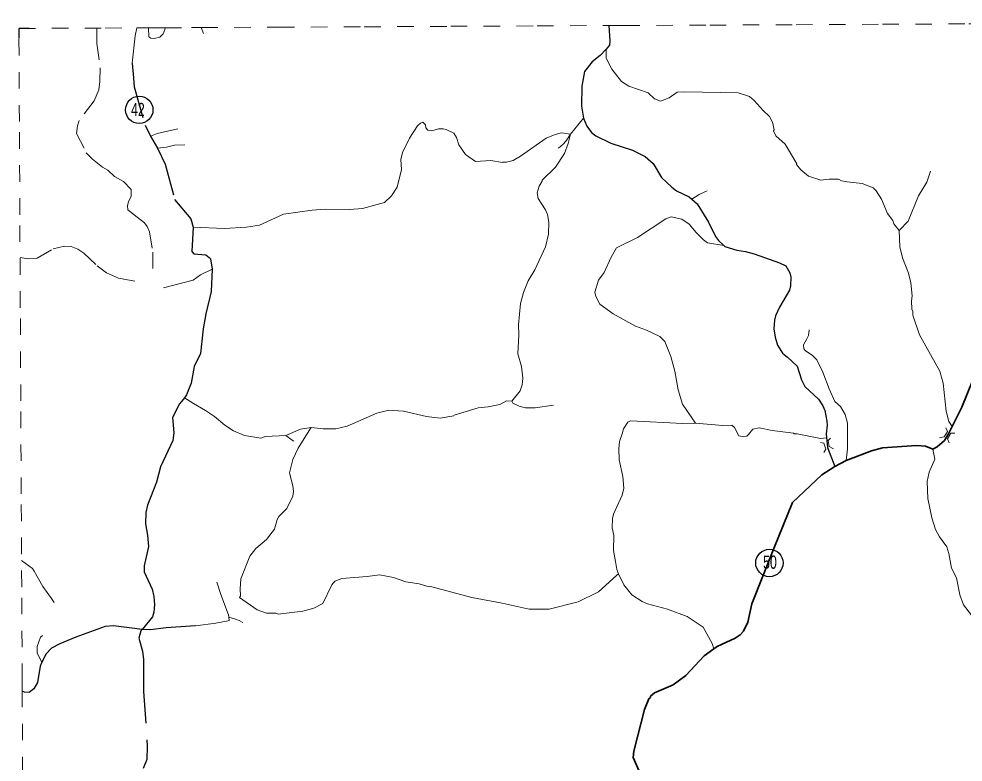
# Model space of a CAD drawing. Extents: x 423 to 448.8, y 7456.3 to 7484.
# Drawn here: x 422.99 to 428.72, y 7479.48 to 7483.99 of the extents above; entities that cross this region are included whole.
import ezdxf
from ezdxf.enums import TextEntityAlignment as Align

# ---------------------------------------------------------------- set-up
doc = ezdxf.new("R2010")
doc.units = 0
doc.header["$LTSCALE"] = 0.032
for name, pattern in [('LONG_DASHED', [7.5, 6, -1.5]), ('MEDIUM_DASHED', [4.5, 3, -1.5]), ('SHORT_DASHED', [2.7, 1.5, -1.2])]:
    doc.linetypes.add(name, pattern=pattern)
for name, color, linetype, lineweight in [('11', 7, 'Continuous', 13), ('13', 7, 'Continuous', 25), ('2', 7, 'Continuous', 35), ('35', 7, 'SHORT_DASHED', 13), ('4', 7, 'LONG_DASHED', 25), ('5', 7, 'LONG_DASHED', 13), ('6', 7, 'MEDIUM_DASHED', 13), ('63', 7, 'Continuous', 25), ('7', 7, 'Continuous', 13)]:
    doc.layers.add(name, color=color, linetype=linetype, lineweight=lineweight)
doc.layers.add('61', color=7, linetype='Continuous')

msp = doc.modelspace()

# ---------------------------------------------------------------- linework, layer by layer
at = {"layer": '11'}
for points in [[(428.6171, 7481.5036), (428.6262, 7481.4826), (428.6052, 7481.4497), (428.5787, 7481.4442)], [(428.6363, 7481.414), (428.6262, 7481.4369), (428.6473, 7481.4716), (428.6711, 7481.4716)], [(427.857, 7481.4151), (427.8759, 7481.4102), (427.8877, 7481.3745), (427.8767, 7481.3535)], [(427.916, 7481.4405), (427.902, 7481.4262), (427.9077, 7481.3902), (427.9343, 7481.3762)]]:
    msp.add_lwpolyline(points, dxfattribs=at)
at = {"layer": '13'}
for centre in [(423.7237, 7483.4329), (427.5458, 7480.684)]:
    msp.add_circle(centre, 0.083, dxfattribs=at)
at = {"layer": '2'}
msp.add_lwpolyline([(426.7706, 7479.388), (426.7191, 7479.5039), (426.7242, 7479.5426), (426.7887, 7479.7951), (426.8153, 7479.8603), (426.8247, 7479.868), (426.8256, 7479.8758), (426.8488, 7479.8956), (426.9622, 7479.9445), (427.0386, 7480.002), (427.1511, 7480.1205), (427.2096, 7480.1634), (427.2284, 7480.1772), (427.3383, 7480.2279), (427.3692, 7480.2477), (427.3899, 7480.2709), (427.4156, 7480.3259), (427.4397, 7480.4358), (427.5728, 7480.7716), (427.6859, 7481.0507), (427.865, 7481.2198), (427.9421, 7481.2701), (428.0118, 7481.3054), (428.1647, 7481.3636), (428.2321, 7481.3822), (428.4377, 7481.3968), (428.4926, 7481.3933), (428.537, 7481.3736), (428.5638, 7481.3893), (428.6077, 7481.4277), (428.6343, 7481.4715), (428.6549, 7481.5131), (428.7125, 7481.6296), (428.7786, 7481.7893)], dxfattribs=at)
at = {"layer": '35'}
for points in [[(426.5714, 7483.9447), (426.6604, 7483.9451), (427.1842, 7483.9476), (427.7081, 7483.9501), (428.232, 7483.9526), (428.7559, 7483.9551), (429.2797, 7483.9575), (429.8036, 7483.9599), (430.3275, 7483.9623), (430.8513, 7483.9647), (431.3752, 7483.9671), (431.8991, 7483.9695), (432.4229, 7483.9718), (432.9468, 7483.9741), (433.4707, 7483.9764), (433.9946, 7483.9787), (434.5184, 7483.981), (435.0423, 7483.9832), (435.5128, 7483.9852)], [(422.9932, 7483.927), (423.5171, 7483.9296), (423.7097, 7483.9306), (423.7804, 7483.9309), (423.8803, 7483.9314)], [(423.0136, 7479.9058), (423.0133, 7479.9732), (423.0104, 7480.538), (423.0075, 7481.1029), (423.0047, 7481.6677), (423.0018, 7482.2325), (422.999, 7482.7973), (422.9961, 7483.3622), (422.9932, 7483.927)], [(423.8803, 7483.9314), (424.041, 7483.9322), (424.0999, 7483.9325)], [(424.0999, 7483.9325), (424.5649, 7483.9348), (425.0887, 7483.9374), (425.6126, 7483.94), (426.1365, 7483.9426), (426.5714, 7483.9447)], [(423.0308, 7476.517), (423.0305, 7476.5843), (423.0276, 7477.1491), (423.0247, 7477.7139), (423.0219, 7478.2787), (423.019, 7478.8436), (423.0161, 7479.4084), (423.0136, 7479.9058)]]:
    msp.add_lwpolyline(points, dxfattribs=at)
at = {"layer": '4'}
for points in [[(426.5714, 7483.9447), (426.5778, 7483.853), (426.5751, 7483.8255), (426.5568, 7483.8008), (426.5193, 7483.7628), (426.47, 7483.7251), (426.4253, 7483.6658), (426.4091, 7483.5774), (426.4056, 7483.4555), (426.4185, 7483.3833), (426.4383, 7483.3352), (426.4666, 7483.2965), (426.494, 7483.2751), (426.5843, 7483.2313), (426.7148, 7483.1883), (426.7921, 7483.1505), (426.8402, 7483.1076), (426.8917, 7483.0235), (426.9544, 7482.9634), (426.9828, 7482.9427), (427.0601, 7482.9058), (427.0756, 7482.892), (427.1073, 7482.8637), (427.176, 7482.752), (427.2198, 7482.6653), (427.2378, 7482.6404), (427.2695, 7482.6109), (427.2756, 7482.6052), (427.3486, 7482.5829), (427.4019, 7482.5743), (427.4534, 7482.5597), (427.608, 7482.5047), (427.6449, 7482.4876), (427.6707, 7482.4438), (427.6758, 7482.418), (427.6733, 7482.3647), (427.6672, 7482.339), (427.608, 7482.2359), (427.5831, 7482.1827), (427.5762, 7482.1569), (427.5728, 7482.1054), (427.5814, 7482.0538), (427.5943, 7482.0048), (427.6258, 7481.9563), (427.6561, 7481.9336), (427.7136, 7481.8778), (427.7403, 7481.7945), (427.7609, 7481.7549), (427.8433, 7481.6776), (427.8699, 7481.6373), (427.8819, 7481.6098), (427.894, 7481.5454), (427.8957, 7481.5196), (427.8897, 7481.4681), (427.8976, 7481.3847), (427.9421, 7481.2701)], [(423.6808, 7483.7168), (423.6851, 7483.6703), (423.6872, 7483.6521), (423.6934, 7483.5723), (423.7588, 7483.3402), (423.7921, 7483.2734), (423.8341, 7483.2012), (423.8797, 7483.1033), (423.9381, 7482.8895), (424.0356, 7482.7714), (424.0498, 7482.722), (424.0429, 7482.5743), (424.0541, 7482.5597), (424.1263, 7482.5528), (424.1469, 7482.5382), (424.1546, 7482.5287), (424.1649, 7482.4661), (424.1589, 7482.3321), (424.1263, 7482.1947), (424.1108, 7482.1054), (424.0948, 7481.9546), (424.0575, 7481.8752), (424.0378, 7481.7756), (424.0103, 7481.7043), (423.9975, 7481.6861), (423.9899, 7481.6753), (423.9677, 7481.6491), (423.9251, 7481.567), (423.9322, 7481.4733), (423.9278, 7481.4269), (423.8522, 7481.2671), (423.8274, 7481.1744), (423.7732, 7481.0353), (423.7629, 7480.9906), (423.7612, 7480.9219), (423.7741, 7480.8532), (423.7801, 7480.7845), (423.7526, 7480.6677), (423.7526, 7480.6307), (423.8016, 7480.5251), (423.8119, 7480.4804), (423.8162, 7480.4323), (423.8119, 7480.386), (423.8033, 7480.3568), (423.7405, 7480.2811)], [(423.7405, 7480.2811), (423.568, 7480.3018), (423.5165, 7480.2984), (423.3396, 7480.2348), (423.2417, 7480.1944), (423.1918, 7480.1678), (423.1592, 7480.1334), (423.133, 7480.0827), (423.1222, 7480.0579), (423.1062, 7479.9599), (423.084, 7479.92), (423.0562, 7479.8973), (423.0276, 7479.901), (423.0136, 7479.9058)], [(424.0641, 7480.3034), (423.8867, 7480.2907), (423.7915, 7480.2792), (423.7431, 7480.2808), (423.7405, 7480.2811)], [(423.7405, 7480.2811), (423.7334, 7480.2726), (423.7218, 7480.2284), (423.7423, 7480.1489), (423.7492, 7480.0991), (423.7492, 7479.9033), (423.7724, 7479.5735), (423.769, 7479.4911), (423.7475, 7479.4369)]]:
    msp.add_lwpolyline(points, dxfattribs=at)
at = {"layer": '5'}
msp.add_line((424.1138, 7483.8962), (424.0999, 7483.9325), dxfattribs=at)
for points in [[(423.7097, 7483.9306), (423.699, 7483.8816), (423.6808, 7483.7168)], [(423.7804, 7483.9309), (423.7824, 7483.8768), (423.7932, 7483.8672), (423.8136, 7483.8663), (423.8481, 7483.8748), (423.8685, 7483.8946), (423.8781, 7483.9201), (423.8803, 7483.9314)], [(429.3835, 7479.8883), (429.3724, 7480.0458), (429.3622, 7480.0783), (429.3419, 7480.1191), (429.3058, 7480.1432), (429.1276, 7480.0928), (429.0864, 7480.0868), (429.0412, 7480.0976), (428.8001, 7480.3335), (428.7712, 7480.3671), (428.724, 7480.4299), (428.7018, 7480.4915), (428.6805, 7480.5938), (428.6509, 7480.6527), (428.6352, 7480.7421), (428.6232, 7480.7819), (428.5785, 7480.8437), (428.5535, 7480.8875), (428.5321, 7480.958), (428.5077, 7481.0752), (428.504, 7481.1776), (428.516, 7481.2353), (428.55, 7481.314), (428.537, 7481.3736)], [(424.0641, 7480.3034), (424.1872, 7480.3182), (424.2529, 7480.3314)]]:
    msp.add_lwpolyline(points, dxfattribs=at)
at = {"layer": '6'}
for points in [[(423.4651, 7483.9293), (423.4658, 7483.8368), (423.4859, 7483.6892), (423.4847, 7483.6049), (423.4773, 7483.5538), (423.4495, 7483.4889), (423.3591, 7483.3694), (423.3482, 7483.3361), (423.3437, 7483.29), (423.4022, 7483.1729), (423.4405, 7483.1338), (423.5009, 7483.0848), (423.5319, 7483.0664), (423.5741, 7483.0285), (423.6283, 7482.9994), (423.6751, 7482.9497), (423.6745, 7482.9066), (423.6591, 7482.8765), (423.6521, 7482.8508), (423.6539, 7482.8276), (423.7114, 7482.7812), (423.7543, 7482.7478), (423.7715, 7482.7246), (423.7859, 7482.6935), (423.8051, 7482.57), (423.8073, 7482.4279)], [(423.0003, 7482.5376), (423.0495, 7482.5291), (423.1051, 7482.5339), (423.2012, 7482.5906), (423.2709, 7482.6061), (423.3095, 7482.6052), (423.3499, 7482.5872), (423.3868, 7482.564), (423.4688, 7482.4875), (423.5244, 7482.4443), (423.5985, 7482.4119), (423.6957, 7482.3933)], [(423.137, 7480.2433), (423.1244, 7480.2333), (423.1031, 7480.1781), (423.1031, 7480.1364), (423.133, 7480.0827)]]:
    msp.add_lwpolyline(points, dxfattribs=at)
at = {"layer": '63'}
msp.add_lwpolyline([(423.0548, 7483.927), (422.9932, 7483.927), (422.9932, 7483.8663)], dxfattribs=at)
at = {"layer": '7'}
msp.add_line((426.3404, 7483.2851), (426.4185, 7483.3833), dxfattribs=at)
for points in [[(428.3325, 7482.7006), (428.3002, 7482.7417), (428.2957, 7482.7615), (428.2624, 7482.8036), (428.226, 7482.8906), (428.1946, 7482.9427), (428.1757, 7482.9608), (428.1095, 7482.9857), (428.0184, 7482.9961), (427.984, 7483.0033), (427.9661, 7483.0123), (427.908, 7483.0118), (427.8584, 7483.0065), (427.7841, 7483.0317), (427.7368, 7483.0698), (427.7111, 7483.1007), (427.7125, 7483.1067), (427.6415, 7483.2253), (427.5848, 7483.2759), (427.5719, 7483.3069), (427.5746, 7483.3113), (427.5651, 7483.3584), (427.5468, 7483.3937), (427.5075, 7483.4288), (427.4542, 7483.4906), (427.425, 7483.5139), (427.3563, 7483.537), (427.034, 7483.5432), (426.9869, 7483.5407), (426.9374, 7483.506), (426.8854, 7483.4861), (426.8483, 7483.501), (426.8111, 7483.5358), (426.6935, 7483.5761), (426.6489, 7483.6058), (426.5894, 7483.6801), (426.5548, 7483.747), (426.5568, 7483.8008)], [(424.0498, 7482.722), (424.2382, 7482.7128), (424.3745, 7482.7206), (424.4528, 7482.7333), (424.5982, 7482.7995), (424.7731, 7482.8249), (424.8519, 7482.8301), (424.9991, 7482.8289), (425.0779, 7482.8352), (425.2113, 7482.8721), (425.2533, 7482.9107), (425.2889, 7482.9649), (425.3136, 7483.0704), (425.3107, 7483.1321), (425.3211, 7483.1736), (425.3619, 7483.2618), (425.412, 7483.3373), (425.4292, 7483.3534), (425.443, 7483.3592), (425.4603, 7483.3419), (425.4614, 7483.3234), (425.4741, 7483.3096), (425.4983, 7483.305), (425.5397, 7483.3172), (425.5679, 7483.3185), (425.5845, 7483.3131), (425.6311, 7483.2918), (425.6472, 7483.2664), (425.6621, 7483.2203), (425.7029, 7483.1621), (425.7628, 7483.1206), (425.8554, 7483.1269), (425.9279, 7483.1131), (425.9279, 7483.1166), (425.9508, 7483.1156), (425.9913, 7483.1257), (426.0368, 7483.1518), (426.1924, 7483.2607), (426.2457, 7483.2847), (426.2846, 7483.2943), (426.3404, 7483.2851)], [(423.7921, 7483.2734), (423.8319, 7483.2907), (423.9567, 7483.3174)], [(426.3404, 7483.2851), (426.3258, 7483.2289), (426.3028, 7483.1675), (426.2491, 7483.0854), (426.1669, 7483.0072), (426.1677, 7483.0011), (426.1488, 7482.9711), (426.1376, 7482.9307), (426.1436, 7482.8963), (426.1883, 7482.8276), (426.1995, 7482.7993), (426.2081, 7482.752), (426.2055, 7482.6791), (426.1875, 7482.6026), (426.123, 7482.4635), (426.0835, 7482.3965), (426.0552, 7482.3243), (426.0363, 7482.2591), (426.0234, 7482.1294), (426.026, 7482.0659), (426.0209, 7481.9533), (426.0423, 7481.876), (426.0501, 7481.8056), (426.0458, 7481.7653), (426.0346, 7481.7283), (425.9831, 7481.6648)], [(426.2638, 7483.2004), (426.2776, 7483.2096), (426.2991, 7483.2287), (426.3182, 7483.251), (426.3404, 7483.2851)], [(423.8341, 7483.2012), (423.8879, 7483.2066), (423.9363, 7483.2181), (424, 7483.2206)], [(428.3325, 7482.7006), (428.3874, 7482.7588), (428.4506, 7482.9109), (428.5019, 7482.9954), (428.5235, 7483.0612)], [(427.1691, 7482.9429), (427.119, 7482.9194), (427.0756, 7482.892)], [(427.0977, 7481.5329), (427.0195, 7481.6478), (426.9921, 7481.7355), (426.9728, 7481.8478), (426.9489, 7481.9376), (426.9109, 7482.0272), (426.8805, 7482.0573), (426.7997, 7482.0975), (426.7345, 7482.1217), (426.5988, 7482.1955), (426.5181, 7482.2548), (426.4932, 7482.3003), (426.4879, 7482.3263), (426.5084, 7482.4009), (426.544, 7482.4474), (426.5858, 7482.5398), (426.6181, 7482.5962), (426.7455, 7482.659), (426.9172, 7482.7718), (426.9503, 7482.7838), (427.015, 7482.7697), (427.0601, 7482.7387), (427.1009, 7482.6894), (427.1459, 7482.6442), (427.1713, 7482.6259), (427.2695, 7482.6109)], [(428.6549, 7481.5131), (428.634, 7481.5417), (428.6188, 7481.6046), (428.5993, 7481.7752), (428.5796, 7481.8487), (428.4565, 7482.0685), (428.417, 7482.1869), (428.417, 7482.2093), (428.4109, 7482.2234), (428.4084, 7482.2745), (428.4119, 7482.3054), (428.4045, 7482.3845), (428.3904, 7482.4429), (428.3539, 7482.5349), (428.3363, 7482.6018), (428.3325, 7482.7006)], [(423.8699, 7482.3529), (424.0506, 7482.4005), (424.0949, 7482.4322), (424.1649, 7482.4661)], [(427.7873, 7482.0985), (427.7825, 7482.0651), (427.7721, 7482.0432), (427.7526, 7482.0083), (427.7547, 7481.983), (427.7654, 7481.9719), (427.8047, 7481.9454), (427.8335, 7481.9166), (427.8708, 7481.8426), (427.9079, 7481.7413)], [(427.9079, 7481.7413), (427.9426, 7481.6628), (427.9779, 7481.6337), (428.0062, 7481.5847), (428.0196, 7481.5331), (428.0188, 7481.3766), (428.0118, 7481.3054)], [(423.9975, 7481.6861), (424.0516, 7481.651), (424.1252, 7481.609), (424.1791, 7481.5722), (424.2428, 7481.5192), (424.2954, 7481.4863), (424.3611, 7481.4573), (424.4603, 7481.4422), (424.4892, 7481.4514), (424.6128, 7481.458)], [(425.9831, 7481.6648), (425.9518, 7481.6678), (425.9106, 7481.6452), (425.8396, 7481.6313), (425.7795, 7481.6253), (425.6344, 7481.5815), (425.631, 7481.5772), (425.5493, 7481.5626), (425.4661, 7481.5737), (425.326, 7481.6046), (425.2384, 7481.6107), (425.1646, 7481.5935), (424.9842, 7481.5136), (424.9151, 7481.4974), (424.8387, 7481.4984), (424.7666, 7481.5063)], [(426.2358, 7481.6408), (426.1249, 7481.6262), (426.0669, 7481.6262), (426.0289, 7481.6364), (425.9895, 7481.6539), (425.9831, 7481.6648)], [(424.7666, 7481.5063), (424.7541, 7481.4887), (424.6864, 7481.3814), (424.6541, 7481.3126), (424.6357, 7481.2319), (424.656, 7481.1522), (424.659, 7481.1183), (424.655, 7481.0903), (424.6177, 7481.0156), (424.5694, 7480.9667), (424.5594, 7480.9478), (424.5445, 7480.8889), (424.4962, 7480.8261), (424.43, 7480.7713), (424.3932, 7480.7245), (424.34, 7480.5888), (424.3355, 7480.528), (424.3385, 7480.4851), (424.332, 7480.4752), (424.4389, 7480.3997), (424.4963, 7480.3794), (424.5522, 7480.3791), (424.5668, 7480.373), (424.7162, 7480.3919), (424.7824, 7480.4106), (424.8365, 7480.4375), (424.8918, 7480.5509), (424.9097, 7480.5736), (424.9517, 7480.5899), (425.1065, 7480.6012), (425.1806, 7480.6125), (425.2655, 7480.5965), (425.3415, 7480.5698), (425.4205, 7480.5577), (425.4827, 7480.5395), (425.4901, 7480.5414), (425.7414, 7480.4745), (425.9246, 7480.4409), (426.0887, 7480.404), (426.2096, 7480.4038), (426.3867, 7480.4478), (426.5089, 7480.5081), (426.6176, 7480.6074), (426.6313, 7480.6176)], [(424.6128, 7481.458), (424.7015, 7481.4955), (424.7666, 7481.5063)], [(427.0977, 7481.5329), (427.0201, 7481.5295), (426.7035, 7481.5461), (426.6866, 7481.5391), (426.6617, 7481.4972), (426.6522, 7481.4673), (426.6367, 7481.4203), (426.6332, 7481.3756), (426.6347, 7481.3089), (426.6563, 7481.2092), (426.6637, 7481.1385), (426.6529, 7481.0953), (426.6102, 7481.0029), (426.6009, 7480.9799), (426.594, 7480.9543), (426.592, 7480.8979), (426.6018, 7480.8503), (426.6013, 7480.7607), (426.6131, 7480.6925), (426.621, 7480.6439), (426.6313, 7480.6176)], [(427.0977, 7481.5329), (427.2636, 7481.5179), (427.3188, 7481.5197), (427.334, 7481.5059), (427.3612, 7481.456), (427.3916, 7481.4498), (427.4087, 7481.4543), (427.4199, 7481.4638), (427.4456, 7481.4964), (427.4834, 7481.5042), (427.5624, 7481.4887), (427.6918, 7481.4722), (427.6965, 7481.4681), (427.7153, 7481.4681), (427.8555, 7481.4397), (427.8921, 7481.4426)], [(424.6128, 7481.458), (424.6503, 7481.4297), (424.6609, 7481.4224)], [(423.0096, 7480.6985), (423.0754, 7480.6504), (423.085, 7480.6337), (423.1385, 7480.542), (423.1917, 7480.4693), (423.2066, 7480.4438)], [(426.6313, 7480.6176), (426.6632, 7480.5518), (426.711, 7480.491), (426.7752, 7480.4502), (426.8067, 7480.4366), (426.9269, 7480.404), (427.048, 7480.3584), (427.144, 7480.2948), (427.1987, 7480.1946), (427.2096, 7480.1634)], [(424.266, 7480.3558), (424.2643, 7480.3685), (424.2176, 7480.4921), (424.195, 7480.5671)], [(424.2529, 7480.3314), (424.2688, 7480.3356), (424.266, 7480.3558)], [(424.266, 7480.3558), (424.3079, 7480.343), (424.3292, 7480.3349), (424.3511, 7480.3227)]]:
    msp.add_lwpolyline(points, dxfattribs=at)

# ---------------------------------------------------------------- texts
at = {"layer": '61', "width": 0.7}
for s, p in [('42', (423.7151, 7483.3955)), ('50', (427.5494, 7480.6491))]:
    msp.add_text(s, height=0.08, dxfattribs=at).set_placement(p, align=Align.CENTER)

doc.saveas('drawing.dxf')
